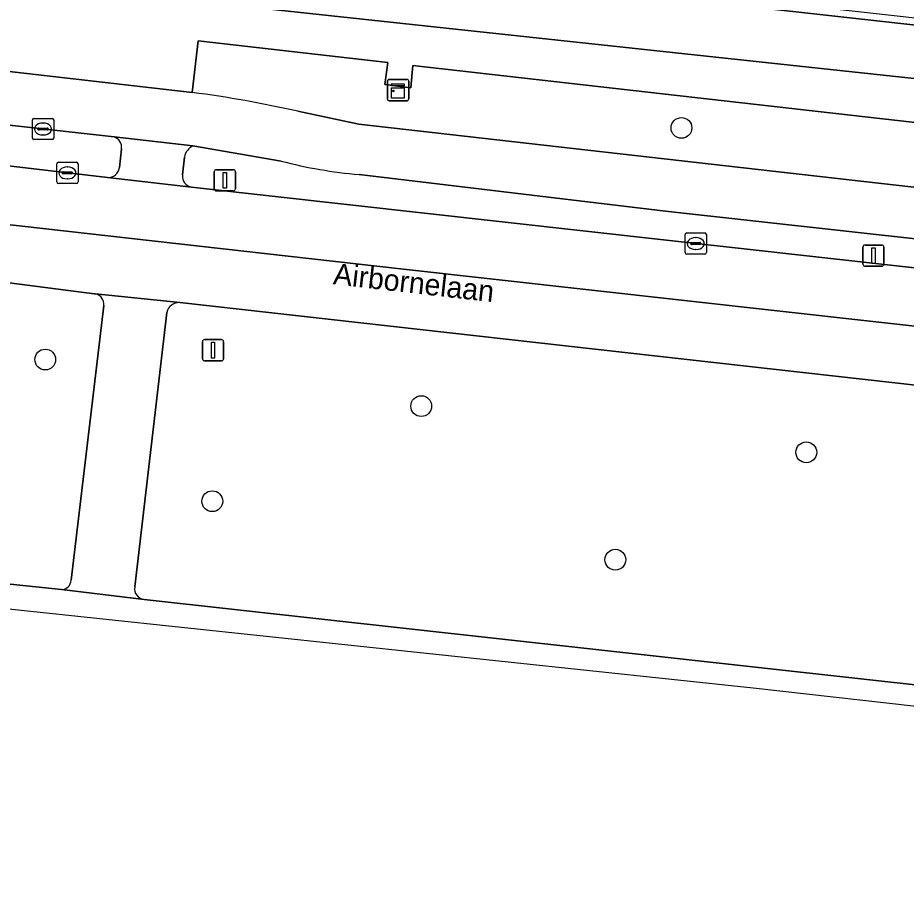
# Model space of a CAD drawing. Extents: x 162026 to 163502, y 387295 to 388169.
# Drawn here: x 162202.39 to 162244.15, y 387396.97 to 387438.04 of the extents above; entities that cross this region are included whole.
import ezdxf

# ---------------------------------------------------------------- set-up
doc = ezdxf.new("R2010")
doc.units = 0
for name, color, linetype in [('IMGEO_Berm_groen', 7, 'Continuous'), ('IMGEO_Boom', 7, 'Continuous'), ('IMGEO_Fietspad_gesloten', 7, 'Continuous'), ('IMGEO_Kast', 7, 'Continuous'), ('IMGEO_Kolk', 7, 'Continuous'), ('IMGEO_Lichtmast', 7, 'Continuous'), ('IMGEO_Muur', 7, 'Continuous'), ('IMGEO_Openbare_ruimte_label', 7, 'Continuous'), ('IMGEO_Rijbaan_lokaal_gesloten', 7, 'Continuous'), ('IMGEO_Verkeersbordpaal', 7, 'Continuous'), ('IMGEO_Verkeerseiland_gesloten', 7, 'Continuous'), ('IMGEO_Verkeerseiland_groen', 7, 'Continuous'), ('IMGEO_Verkeerseiland_open', 7, 'Continuous'), ('IMGEO_Voetpad_open', 7, 'Continuous')]:
    doc.layers.add(name, color=color, linetype=linetype)

msp = doc.modelspace()

# ---------------------------------------------------------------- linework, layer by layer
at = {"layer": 'IMGEO_Berm_groen'}
for points in [[(162220.967, 387435.797), (162220.862, 387434.744), (162219.653, 387434.899), (162219.785, 387435.943), (162210.867, 387436.961), (162210.591, 387434.524)], [(162215.56, 387433.64), (162218.416, 387433.043), (162257.342, 387428.622), (162257.686, 387431.621), (162220.967, 387435.797)]]:
    msp.add_lwpolyline(points, dxfattribs=at)
msp.add_arc((162203.775, 387381.801), 53.162, 77.1917, 82.6332, dxfattribs=at)
at = {"layer": 'IMGEO_Boom'}
for centre in [(162233.585, 387432.859), (162203.686, 387421.97), (162221.357, 387419.779), (162239.453, 387417.607), (162211.536, 387415.307), (162230.479, 387412.558)]:
    msp.add_circle(centre, 0.489, dxfattribs=at)
at = {"layer": 'IMGEO_Fietspad_gesloten'}
for points in [[(162098.738, 387443.599), (162099.123, 387443.677), (162100.125, 387443.584), (162100.105, 387443.368), (162114.071, 387441.73), (162182.412, 387434.134), (162182.426, 387434.32), (162183.642, 387434.22), (162200.438, 387433.156), (162206.924, 387432.438), (162210.629, 387432.019), (162214.769, 387431.3)], [(162210.591, 387434.524), (162200.891, 387435.635), (162199.508, 387435.718), (162197.751, 387435.824)], [(162218.44, 387430.671), (162232.83, 387428.951), (162295.396, 387422.021), (162295.656, 387424.353), (162260.33, 387428.284), (162257.342, 387428.622), (162218.416, 387433.043), (162215.56, 387433.64)]]:
    msp.add_lwpolyline(points, dxfattribs=at)
for centre, radius, start, end in [((162203.775, 387381.801), 53.162, 77.1917, 82.6332), ((162220.229, 387452.14), 21.544, 255.3183, 265.2361)]:
    msp.add_arc(centre, radius, start, end, dxfattribs=at)
at = {"layer": 'IMGEO_Kast'}
for p, q in [((162219.841, 387435.137), (162220.682, 387435.137)), ((162220.682, 387435.137), (162219.841, 387435.137)), ((162219.766, 387434.212), (162219.766, 387435.053)), ((162219.766, 387435.053), (162219.766, 387434.212)), ((162220.766, 387435.062), (162220.766, 387434.221)), ((162220.766, 387434.221), (162220.766, 387435.062)), ((162220.691, 387434.137), (162219.85, 387434.137)), ((162219.85, 387434.137), (162220.691, 387434.137))]:
    msp.add_line(p, q, dxfattribs=at)
for points in [[(162219.961, 387434.927), (162220.561, 387434.927), (162220.561, 387434.842), (162219.961, 387434.842), (162219.961, 387434.927)], [(162219.961, 387434.752), (162220.561, 387434.752), (162220.561, 387434.263), (162219.961, 387434.263), (162219.961, 387434.752)]]:
    msp.add_lwpolyline(points, dxfattribs=at)
msp.add_circle((162220.045, 387434.601), 0.0377, dxfattribs=at)
for centre, start, end in [((162219.844, 387435.059), 92.4484, 184.2845), ((162219.844, 387435.059), 92.4484, 184.2845), ((162220.688, 387435.059), 2.4484, 94.2845), ((162220.688, 387435.059), 2.4484, 94.2845), ((162219.844, 387434.215), 182.4484, 274.2845), ((162219.844, 387434.215), 182.4484, 274.2845), ((162220.688, 387434.215), 272.4484, 4.2845), ((162220.688, 387434.215), 272.4484, 4.2845)]:
    msp.add_arc(centre, 0.0779, start, end, dxfattribs=at)
at = {"layer": 'IMGEO_Kolk'}
for p, q in [((162203.081, 387432.382), (162203.081, 387433.234)), ((162203.156, 387433.308), (162204.008, 387433.308)), ((162203.569, 387433.088), (162203.594, 387433.088)), ((162204.082, 387433.234), (162204.082, 387432.382)), ((162203.34, 387432.802), (162203.34, 387432.814)), ((162203.778, 387432.765), (162203.38, 387432.765)), ((162203.383, 387432.851), (162203.781, 387432.851)), ((162203.824, 387432.814), (162203.824, 387432.802)), ((162204.008, 387432.308), (162203.156, 387432.308)), ((162203.592, 387432.528), (162203.567, 387432.528)), ((162204.227, 387430.319), (162204.227, 387431.171)), ((162204.302, 387431.245), (162205.154, 387431.245)), ((162204.715, 387431.025), (162204.74, 387431.025)), ((162205.228, 387431.171), (162205.228, 387430.319)), ((162204.486, 387430.739), (162204.486, 387430.751)), ((162204.924, 387430.702), (162204.526, 387430.702)), ((162204.529, 387430.788), (162204.927, 387430.788)), ((162204.97, 387430.751), (162204.97, 387430.739)), ((162205.154, 387430.245), (162204.302, 387430.245)), ((162204.738, 387430.465), (162204.713, 387430.465)), ((162233.758, 387426.998), (162233.758, 387427.85)), ((162233.833, 387427.924), (162234.685, 387427.924)), ((162234.246, 387427.704), (162234.271, 387427.704)), ((162234.759, 387427.85), (162234.759, 387426.998)), ((162234.017, 387427.418), (162234.017, 387427.43)), ((162234.455, 387427.381), (162234.057, 387427.381)), ((162234.06, 387427.467), (162234.458, 387427.467)), ((162234.501, 387427.43), (162234.501, 387427.418)), ((162234.685, 387426.924), (162233.833, 387426.924)), ((162234.269, 387427.144), (162234.244, 387427.144))]:
    msp.add_line(p, q, dxfattribs=at)
for points in [[(162203.081, 387432.382), (162203.081, 387433.234)], [(162203.156, 387433.308), (162204.008, 387433.308)], [(162204.082, 387433.234), (162204.082, 387432.382)], [(162204.008, 387432.308), (162203.156, 387432.308)], [(162204.227, 387430.319), (162204.227, 387431.171)], [(162204.302, 387431.245), (162205.154, 387431.245)], [(162205.228, 387431.171), (162205.228, 387430.319)], [(162205.154, 387430.245), (162204.302, 387430.245)], [(162233.758, 387426.998), (162233.758, 387427.85)], [(162233.833, 387427.924), (162234.685, 387427.924)], [(162234.759, 387427.85), (162234.759, 387426.998)], [(162234.685, 387426.924), (162233.833, 387426.924)]]:
    msp.add_lwpolyline(points, dxfattribs=at)
for centre, radius, start, end in [((162203.158, 387433.232), 0.0765, 91.552, 178.448), ((162203.158, 387433.232), 0.0765, 91.552, 178.448), ((162204.006, 387433.232), 0.0765, 1.552, 88.448), ((162204.006, 387433.232), 0.0765, 1.552, 88.448), ((162203.38, 387432.811), 0.0403, 85.8775, 175.7526), ((162203.377, 387432.801), 0.0366, 178.938, 274.7102), ((162203.781, 387432.808), 0.043, 264.8664, 352.4533), ((162203.785, 387432.813), 0.0386, 1.7309, 96.639), ((162203.158, 387432.384), 0.0765, 181.552, 268.448), ((162203.158, 387432.384), 0.0765, 181.552, 268.448), ((162204.006, 387432.384), 0.0765, 271.552, 358.448), ((162204.006, 387432.384), 0.0765, 271.552, 358.448), ((162204.304, 387431.169), 0.0765, 91.552, 178.448), ((162204.304, 387431.169), 0.0765, 91.552, 178.448), ((162205.152, 387431.169), 0.0765, 1.552, 88.448), ((162205.152, 387431.169), 0.0765, 1.552, 88.448), ((162204.526, 387430.748), 0.0403, 85.8775, 175.7526), ((162204.523, 387430.738), 0.0366, 178.938, 274.7102), ((162204.927, 387430.745), 0.043, 264.8664, 352.4533), ((162204.931, 387430.75), 0.0386, 1.7309, 96.639), ((162204.304, 387430.321), 0.0765, 181.552, 268.448), ((162204.304, 387430.321), 0.0765, 181.552, 268.448), ((162205.152, 387430.321), 0.0765, 271.552, 358.448), ((162205.152, 387430.321), 0.0765, 271.552, 358.448), ((162233.835, 387427.848), 0.0765, 91.552, 178.448), ((162233.835, 387427.848), 0.0765, 91.552, 178.448), ((162234.683, 387427.848), 0.0765, 1.552, 88.448), ((162234.683, 387427.848), 0.0765, 1.552, 88.448), ((162234.057, 387427.427), 0.0403, 85.8775, 175.7526), ((162234.054, 387427.417), 0.0366, 178.938, 274.7102), ((162234.458, 387427.424), 0.043, 264.8664, 352.4533), ((162234.462, 387427.429), 0.0386, 1.7309, 96.639), ((162233.835, 387427), 0.0765, 181.552, 268.448), ((162233.835, 387427), 0.0765, 181.552, 268.448), ((162234.683, 387427), 0.0765, 271.552, 358.448), ((162234.683, 387427), 0.0765, 271.552, 358.448)]:
    msp.add_arc(centre, radius, start, end, dxfattribs=at)
for centre, major_axis, ratio, start_param, end_param in [((162203.568, 387432.808), (-0.387, 0.002), 0.722429, 4.712389, 7.853982), ((162203.593, 387432.808), (-0.39, 0.002), 0.717154, 1.570796, 4.712389), ((162204.714, 387430.745), (-0.387, 0.002), 0.722429, 4.712389, 7.853982), ((162204.739, 387430.745), (-0.39, 0.002), 0.717154, 1.570796, 4.712389), ((162234.245, 387427.424), (-0.387, 0.002), 0.722429, 4.712389, 7.853982), ((162234.27, 387427.424), (-0.39, 0.002), 0.717154, 1.570796, 4.712389)]:
    msp.add_ellipse(centre, major_axis=major_axis, ratio=ratio, start_param=start_param, end_param=end_param, dxfattribs=at)
at = {"layer": 'IMGEO_Lichtmast'}
for p, q in [((162211.631, 387429.996), (162211.631, 387430.796)), ((162211.631, 387430.796), (162211.631, 387429.996)), ((162211.731, 387430.896), (162212.521, 387430.896)), ((162212.521, 387430.896), (162211.731, 387430.896)), ((162212.621, 387430.796), (162212.621, 387429.996)), ((162212.621, 387429.996), (162212.621, 387430.796)), ((162212.521, 387429.896), (162211.731, 387429.896)), ((162211.731, 387429.896), (162212.521, 387429.896)), ((162242.113, 387426.454), (162242.113, 387427.254)), ((162242.113, 387427.254), (162242.113, 387426.454)), ((162242.213, 387427.354), (162243.003, 387427.354)), ((162243.003, 387427.354), (162242.213, 387427.354)), ((162243.103, 387427.254), (162243.103, 387426.454)), ((162243.103, 387426.454), (162243.103, 387427.254)), ((162243.003, 387426.354), (162242.213, 387426.354)), ((162242.213, 387426.354), (162243.003, 387426.354))]:
    msp.add_line(p, q, dxfattribs=at)
for points in [[(162212.051, 387430.771), (162212.201, 387430.771), (162212.201, 387430.021), (162212.051, 387430.021), (162212.051, 387430.771)], [(162242.533, 387427.229), (162242.683, 387427.229), (162242.683, 387426.479), (162242.533, 387426.479), (162242.533, 387427.229)]]:
    msp.add_lwpolyline(points, dxfattribs=at)
for centre, start, end in [((162211.731, 387430.796), 90, 180), ((162211.731, 387430.796), 90, 180), ((162212.521, 387430.796), 0, 90), ((162212.521, 387430.796), 360, 90), ((162211.731, 387429.996), 180, 270), ((162211.731, 387429.996), 180, 270), ((162212.521, 387429.996), 270, 0), ((162212.521, 387429.996), 270, 0), ((162242.213, 387427.254), 90, 180), ((162242.213, 387427.254), 90, 180), ((162243.003, 387427.254), 0, 90), ((162243.003, 387427.254), 360, 90), ((162242.213, 387426.454), 180, 270), ((162242.213, 387426.454), 180, 270), ((162243.003, 387426.454), 270, 0), ((162243.003, 387426.454), 270, 0)]:
    msp.add_arc(centre, 0.1, start, end, dxfattribs=at)
at = {"layer": 'IMGEO_Muur'}
msp.add_lwpolyline([(162210.221, 387461.801), (162212.136, 387461.606), (162212.17, 387461.941), (162209.946, 387462.167), (162207.357, 387441.991), (162207.558, 387441.965), (162207.542, 387441.833), (162256.589, 387436.362), (162257.281, 387434.901), (162258.397, 387434.776), (162257.76, 387436.226), (162257.608, 387436.571), (162256.384, 387436.706), (162207.699, 387442.138)], close=True, dxfattribs=at)
at = {"layer": 'IMGEO_Rijbaan_lokaal_gesloten'}
for points in [[(162210.565, 387430.071), (162206.617, 387430.521), (162201.414, 387431.138), (162183.608, 387433.186), (162116.314, 387440.645), (162098.953, 387442.66), (162098.932, 387442.459), (162098.611, 387439.619), (162102.254, 387439.258), (162114.714, 387437.842), (162183.549, 387430.393), (162220.386, 387426.232), (162277.847, 387419.821), (162298.401, 387417.501)], [(162298.401, 387417.501), (162277.847, 387419.821), (162220.386, 387426.232), (162183.549, 387430.393), (162114.714, 387437.842)], [(162111.502, 387435.204), (162171.793, 387428.67), (162175.009, 387428.07), (162179.938, 387427.529), (162180.481, 387427.447), (162182.204, 387427.695), (162198.842, 387425.939), (162201.988, 387425.577), (162205.981, 387425.06), (162206.042, 387425.054), (162210.004, 387424.649), (162281.393, 387416.628), (162286.334, 387415.81), (162323.247, 387408.629), (162323.614, 387413.252), (162313.176, 387416.238)], [(162295.377, 387420.586), (162295.212, 387420.616), (162210.565, 387430.071)], [(162096.771, 387421.253), (162141.573, 387416.6), (162155.241, 387415.181), (162202.411, 387410.194), (162236.962, 387406.541), (162321.901, 387396.97), (162322.126, 387398.89), (162278.96, 387402.864), (162208.341, 387410.68), (162204.454, 387411.152), (162200.361, 387411.584), (162177.353, 387414.082), (162176.732, 387414.2), (162106.28, 387422.081)]]:
    msp.add_lwpolyline(points, dxfattribs=at)
at = {"layer": 'IMGEO_Verkeersbordpaal'}
for p, q in [((162211.074, 387422.007), (162211.074, 387422.807)), ((162211.074, 387422.807), (162211.074, 387422.007)), ((162211.174, 387422.907), (162211.964, 387422.907)), ((162211.964, 387422.907), (162211.174, 387422.907)), ((162212.064, 387422.807), (162212.064, 387422.007)), ((162212.064, 387422.007), (162212.064, 387422.807)), ((162211.964, 387421.907), (162211.174, 387421.907)), ((162211.174, 387421.907), (162211.964, 387421.907))]:
    msp.add_line(p, q, dxfattribs=at)
msp.add_lwpolyline([(162211.494, 387422.782), (162211.644, 387422.782), (162211.644, 387422.032), (162211.494, 387422.032), (162211.494, 387422.782)], dxfattribs=at)
for centre, start, end in [((162211.174, 387422.807), 90, 180), ((162211.174, 387422.807), 90, 180), ((162211.964, 387422.807), 0, 90), ((162211.964, 387422.807), 360, 90), ((162211.174, 387422.007), 180, 270), ((162211.174, 387422.007), 180, 270), ((162211.964, 387422.007), 270, 0), ((162211.964, 387422.007), 270, 0)]:
    msp.add_arc(centre, 0.1, start, end, dxfattribs=at)
at = {"layer": 'IMGEO_Verkeerseiland_gesloten'}
for points in [[(162206.924, 387432.438), (162200.438, 387433.156)], [(162207.17, 387430.996), (162207.271, 387431.883)], [(162200.013, 387431.472), (162201.414, 387431.138), (162206.617, 387430.521)]]:
    msp.add_lwpolyline(points, dxfattribs=at)
for centre, radius, start, end in [((162206.756, 387431.947), 0.519, 352.9435, 71.0858), ((162206.627, 387431.068), 0.547, 268.9131, 352.4089)]:
    msp.add_arc(centre, radius, start, end, dxfattribs=at)
at = {"layer": 'IMGEO_Verkeerseiland_groen'}
for points in [[(162206.042, 387425.054), (162205.981, 387425.06), (162201.988, 387425.577)], [(162204.904, 387411.589), (162206.437, 387424.504)], [(162286.334, 387415.81), (162281.393, 387416.628), (162210.004, 387424.649)], [(162209.399, 387424.187), (162207.893, 387411.284)], [(162200.361, 387411.584), (162204.454, 387411.152)], [(162208.341, 387410.68), (162278.96, 387402.864), (162322.126, 387398.89), (162322.228, 387398.884)]]:
    msp.add_lwpolyline(points, dxfattribs=at)
for centre, radius, start, end in [((162205.962, 387424.58), 0.481, 350.9173, 80.4531), ((162209.982, 387424.051), 0.598, 87.8544, 166.8789), ((162204.437, 387411.62), 0.468, 272.1026, 356.218), ((162208.407, 387411.197), 0.521, 170.4101, 262.7202)]:
    msp.add_arc(centre, radius, start, end, dxfattribs=at)
at = {"layer": 'IMGEO_Verkeerseiland_open'}
for points in [[(162214.769, 387431.3), (162210.629, 387432.019)], [(162210.23, 387431.487), (162210.132, 387430.651)], [(162210.565, 387430.071), (162295.212, 387420.616), (162295.396, 387422.021), (162232.83, 387428.951), (162218.44, 387430.671)]]:
    msp.add_lwpolyline(points, dxfattribs=at)
for centre, radius, start, end in [((162210.928, 387431.379), 0.706, 115.0333, 171.2269), ((162220.229, 387452.14), 21.544, 255.3183, 265.2361), ((162210.666, 387430.598), 0.537, 174.3355, 259.151)]:
    msp.add_arc(centre, radius, start, end, dxfattribs=at)
at = {"layer": 'IMGEO_Voetpad_open'}
msp.add_lwpolyline([(162207.542, 387441.833), (162207.232, 387439.213), (162263.167, 387433.177), (162262.078, 387435.683), (162257.76, 387436.226), (162258.397, 387434.776), (162257.281, 387434.901), (162256.589, 387436.362)], close=True, dxfattribs=at)
for points in [[(162338.712, 387424.373), (162335.062, 387425.067), (162334.017, 387425.187), (162314.806, 387427.36), (162314.58, 387427.386), (162309.216, 387427.99), (162263.167, 387433.177), (162207.232, 387439.213)], [(162199.3, 387435.802), (162199.508, 387435.718), (162200.891, 387435.635), (162210.591, 387434.524), (162210.867, 387436.961), (162219.785, 387435.943), (162219.653, 387434.899), (162220.862, 387434.744), (162220.967, 387435.797), (162257.686, 387431.621), (162257.342, 387428.622), (162260.33, 387428.284), (162260.667, 387431.287), (162329.354, 387423.577), (162329.001, 387420.783), (162332.873, 387420.356)], [(162210.629, 387432.019), (162206.924, 387432.438)], [(162207.271, 387431.883), (162207.17, 387430.996)], [(162210.132, 387430.651), (162210.23, 387431.487)], [(162206.617, 387430.521), (162210.565, 387430.071)], [(162210.004, 387424.649), (162206.042, 387425.054)], [(162206.437, 387424.504), (162204.904, 387411.589)], [(162207.893, 387411.284), (162209.399, 387424.187)], [(162204.454, 387411.152), (162208.341, 387410.68)]]:
    msp.add_lwpolyline(points, dxfattribs=at)
for centre, radius, start, end in [((162206.756, 387431.947), 0.519, 352.9435, 71.0858), ((162210.928, 387431.379), 0.706, 115.0333, 171.2269), ((162206.627, 387431.068), 0.547, 268.9131, 352.4089), ((162210.666, 387430.598), 0.537, 174.3355, 259.151), ((162205.962, 387424.58), 0.481, 350.9173, 80.4531), ((162209.982, 387424.051), 0.598, 87.8544, 166.8789), ((162204.437, 387411.62), 0.468, 272.1026, 356.218), ((162208.407, 387411.197), 0.521, 170.4101, 262.7202)]:
    msp.add_arc(centre, radius, start, end, dxfattribs=at)

# ---------------------------------------------------------------- texts
at = {"layer": 'IMGEO_Openbare_ruimte_label'}
msp.add_text('Airbornelaan', height=1, rotation=353.5713, dxfattribs=at).set_placement((162217.187, 387425.514))

doc.saveas('drawing.dxf')
